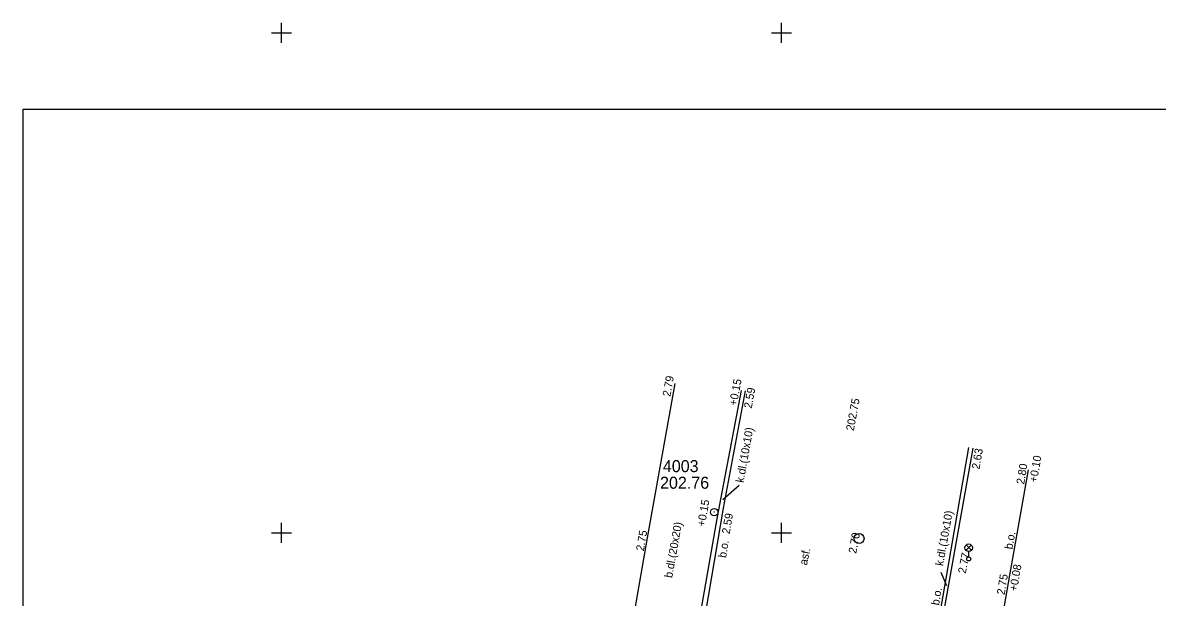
# Model space of a CAD drawing. Extents: x -595938 to -595824, y -1160278 to -1160200.
# Drawn here: x -595937.9 to -595881.2, y -1160228.2 to -1160199.5 of the extents above; entities that cross this region are included whole.
import ezdxf

# ---------------------------------------------------------------- set-up
doc = ezdxf.new("R2010")
doc.units = 0
for name, color, linetype in [('Vrstva 1', 7, 'Continuous'), ('Vrstva 10', 7, 'Continuous'), ('Vrstva 2', 7, 'Continuous'), ('Vrstva 25', 7, 'Continuous'), ('Vrstva 29', 7, 'Continuous'), ('Vrstva 49', 7, 'Continuous'), ('Vrstva 50', 7, 'Continuous'), ('Vrstva 58', 7, 'Continuous'), ('Vrstva 62', 7, 'Continuous'), ('Vrstva 7', 7, 'Continuous')]:
    doc.layers.add(name, color=color, linetype=linetype)

msp = doc.modelspace()

# ---------------------------------------------------------------- linework, layer by layer
at = {"layer": 'Vrstva 1'}
for p, q in [((-595832.94, -1160203.84), (-595937.94, -1160203.84)), ((-595937.94, -1160203.84), (-595937.94, -1160278.09))]:
    msp.add_line(p, q, dxfattribs=at)
at = {"layer": 'Vrstva 10'}
msp.add_lwpolyline([(-595916.78, -1160228.671), (-595907.59, -1160230.32), (-595906.71, -1160225.26), (-595905.33, -1160217.54)], dxfattribs=at)
at = {"layer": 'Vrstva 2'}
msp.add_line((-595903.37, -1160223.97), (-595903.37, -1160223.97), dxfattribs=at)
for radius in [0.188, 0.00896]:
    msp.add_circle((-595903.37, -1160223.97), radius, dxfattribs=at)
at = {"layer": 'Vrstva 25'}
msp.add_circle((-595896.13, -1160225.29), 0.25, dxfattribs=at)
at = {"layer": 'Vrstva 29'}
for p, q in [((-595890.782, -1160225.879), (-595890.518, -1160225.615)), ((-595890.514, -1160225.878), (-595890.778, -1160225.613)), ((-595890.65, -1160226.21), (-595890.65, -1160225.935))]:
    msp.add_line(p, q, dxfattribs=at)
for centre, radius in [((-595890.65, -1160225.748), 0.188), ((-595890.65, -1160226.31), 0.1)]:
    msp.add_circle(centre, radius, dxfattribs=at)
at = {"layer": 'Vrstva 49'}
for p, q in [((-595902.94, -1160223.34), (-595902.13, -1160222.63)), ((-595891.74, -1160227.65), (-595892.02, -1160226.98))]:
    msp.add_line(p, q, dxfattribs=at)
at = {"layer": 'Vrstva 62'}
for p, q in [((-595925, -1160200.5), (-595925, -1160199.5)), ((-595900, -1160200.5), (-595900, -1160199.5)), ((-595925.5, -1160200), (-595924.5, -1160200)), ((-595900.5, -1160200), (-595899.5, -1160200)), ((-595925, -1160225.5), (-595925, -1160224.5)), ((-595900, -1160225.5), (-595900, -1160224.5)), ((-595925.5, -1160225), (-595924.5, -1160225)), ((-595900.5, -1160225), (-595899.5, -1160225))]:
    msp.add_line(p, q, dxfattribs=at)
at = {"layer": 'Vrstva 7'}
for points in [[(-595909.491, -1160260.33), (-595908.59, -1160255.05), (-595908.37, -1160253.74), (-595908, -1160251.52), (-595907.5, -1160248.71), (-595906.27, -1160241.67), (-595906.11, -1160240.93), (-595905.22, -1160236), (-595904.2, -1160229.92), (-595903.2, -1160224.21), (-595902.01, -1160217.89)], [(-595906.11, -1160240.93), (-595905.26, -1160237.41), (-595903.95, -1160229.95), (-595902.9, -1160223.78), (-595901.8, -1160217.9)], [(-595897.85, -1160261.94), (-595896.66, -1160255.15), (-595895.4, -1160247.92), (-595894.18, -1160240.87), (-595892.23, -1160229.88), (-595890.65, -1160220.74)], [(-595897.6, -1160261.97), (-595896.38, -1160254.94), (-595895.2, -1160248.24), (-595893.92, -1160240.87), (-595892.05, -1160229.92), (-595890.42, -1160220.77)], [(-595887.68, -1160221.85), (-595888.66, -1160227.41), (-595890.33, -1160237.01), (-595891.42, -1160243.19), (-595892.43, -1160248.93), (-595888.97, -1160249.568)]]:
    msp.add_lwpolyline(points, dxfattribs=at)

# ---------------------------------------------------------------- texts
at = {"layer": 'Vrstva 2'}
for s, p in [(' 4003', (-595906.16, -1160221.97)), ('202.76 ', (-595906.078, -1160222.8))]:
    msp.add_text(s, height=0.6, dxfattribs=at).set_placement(p)
at = {"layer": 'Vrstva 49'}
for s, rotation, p in [('k.dl.(10x10)', 79.8447, (-595901.903, -1160222.52)), ('k.dl.(10x10)', 79.8447, (-595891.933, -1160226.68)), ('b.dl.(20x20)', 79.8447, (-595905.473, -1160227.28)), ('b.o.', 80.0038, (-595888.466, -1160225.851)), ('b.o.', 80.342, (-595902.782, -1160226.278)), ('asf.', 78.2052, (-595898.736, -1160226.646)), ('b.o.', 79.8992, (-595892.135, -1160228.65))]:
    msp.add_text(s, height=0.4, rotation=rotation, dxfattribs=at).set_placement(p)
at = {"layer": 'Vrstva 50'}
for s, rotation, p in [('+0.15', 79.3366, (-595902.248, -1160218.678)), ('+0.10', 80.0038, (-595887.24, -1160222.509)), ('+0.15', 80.0665, (-595903.839, -1160224.713)), ('+0.08', 80.1317, (-595888.237, -1160227.947))]:
    msp.add_text(s, height=0.4, rotation=rotation, dxfattribs=at).set_placement(p)
at = {"layer": 'Vrstva 58'}
for s, rotation, p in [(' 2.79', 79.8457, (-595905.592, -1160218.362)), (' 2.59', 79.584, (-595901.526, -1160218.952)), (' 202.75', 79.4184, (-595896.422, -1160220.075)), (' 2.63', 80.1621, (-595890.137, -1160221.993)), (' 2.80', 80.5377, (-595887.903, -1160222.75)), (' 2.59', 80.1589, (-595902.627, -1160225.233)), (' 2.75', 80.0106, (-595906.919, -1160226.083)), (' 2.70', 79.4433, (-595896.301, -1160226.207)), (' 2.77', 78.9792, (-595890.825, -1160227.21)), (' 2.75', 80.4383, (-595888.882, -1160228.274))]:
    msp.add_text(s, height=0.4, rotation=rotation, dxfattribs=at).set_placement(p)

doc.saveas('drawing.dxf')
